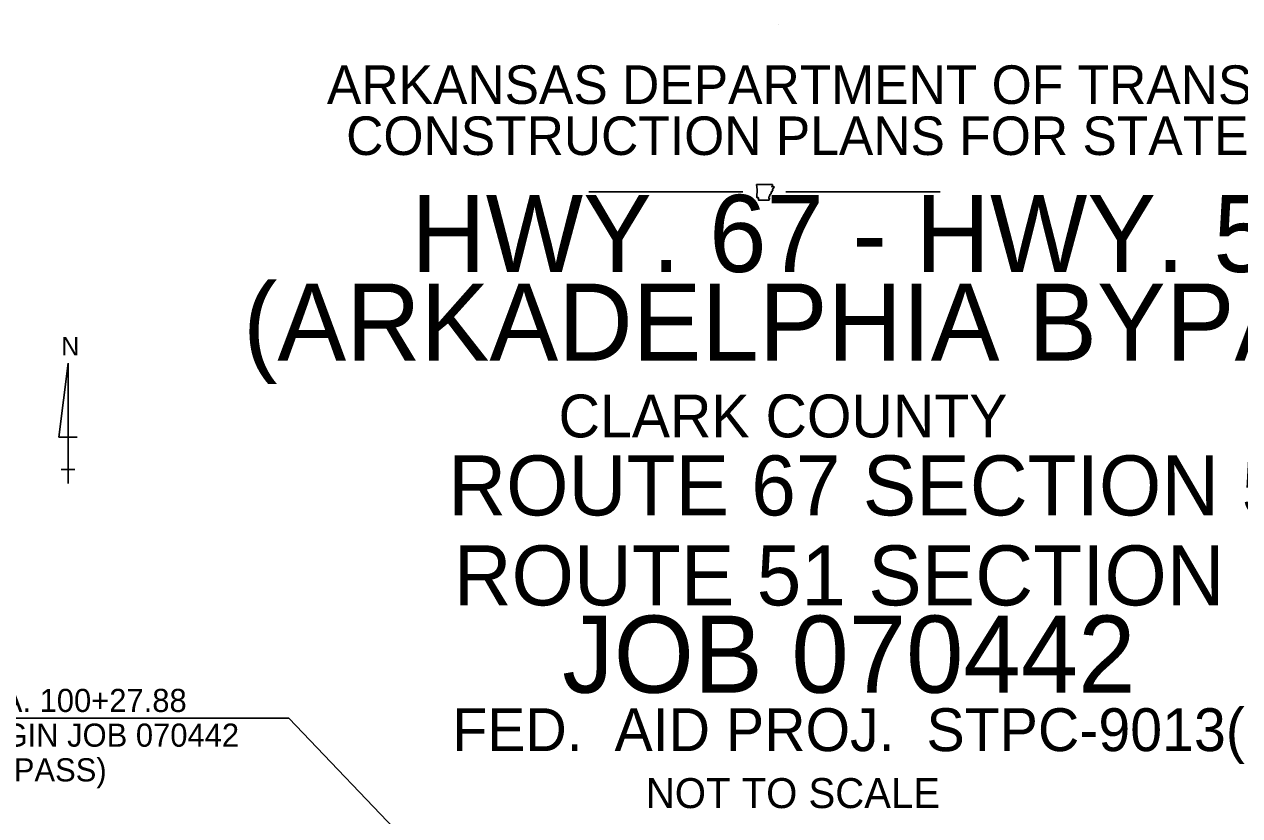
# Model space of a CAD drawing. Extents: x 813775 to 1157140, y 1757555 to 1979907.
# Drawn here: x 897210 to 1039048, y 1887546 to 1979907 of the extents above; entities that cross this region are included whole.
import ezdxf

# ---------------------------------------------------------------- set-up
doc = ezdxf.new("R2010")
doc.units = 0
doc.layers.add('1', color=7, linetype='Continuous')
doc.layers.add('R_Draft', color=7, linetype='Continuous')

msp = doc.modelspace()

# ---------------------------------------------------------------- linework, layer by layer
at = {"layer": '1'}
msp.add_line((985264.2783168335, 1979906.6062498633), (985264.2783168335, 1979906.6062498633), dxfattribs=at)
msp.add_line((985264.2783168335, 1979906.6062498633), (985264.2783168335, 1979906.6062498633), dxfattribs=at)
at = {"layer": 'R_Draft'}
for p, q in [((963082.4982804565, 1960363.5333469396), (981082.498282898, 1960363.5333469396)), ((986082.4982804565, 1960363.5333469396), (1004082.498282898, 1960363.5333469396)), ((902316.5839318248, 1940365.3942293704), (901236.5839318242, 1931725.394229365)), ((902316.5839318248, 1926325.3942296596), (902316.5839318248, 1940365.3942293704)), ((901236.5839318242, 1931725.394229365), (903396.5839318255, 1931725.394229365)), ((901501.5839318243, 1927965.3942296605), (903121.5839318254, 1927965.3942296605)), ((928075.3350066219, 1898928.1496111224), (888711.8381773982, 1898928.1496111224)), ((982982.4770436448, 1841464.5562002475), (928075.3350066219, 1898928.1496111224))]:
    msp.add_line(p, q, dxfattribs=at)
for points in [[(982650.88148172, 1961195.2289559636), (983196.6189818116, 1961194.8914559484), (983675.531481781, 1961195.9039559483), (984240.5064818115, 1961204.678955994), (984502.4064817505, 1961210.7539559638)], [(982690.3689817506, 1959718.6664559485), (982720.7439818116, 1960634.3039559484), (982650.88148172, 1961195.2289559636)], [(984421.406481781, 1960947.1664559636), (984677.5689818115, 1960960.3289559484)], [(984114.6189817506, 1959389.2664559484), (982877.6814817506, 1959391.2914559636), (982877.0064818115, 1959664.3289559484)]]:
    msp.add_lwpolyline(points, dxfattribs=at)
for points in [[(984398.7939818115, 1960300.8539559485), (984391.031481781, 1960291.0664559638), (984379.5564818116, 1960297.1414559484), (984379.5564818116, 1960305.2414559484), (984381.2439818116, 1960313.678955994), (984377.1939818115, 1960319.0789559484), (984370.1064818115, 1960316.7164559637), (984370.1064818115, 1960306.2539559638), (984369.4314818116, 1960296.1289559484), (984367.406481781, 1960281.6164559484), (984372.13148172, 1960277.2289559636), (984382.9314818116, 1960275.8789559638), (984390.69398172, 1960273.8539559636), (984395.4189818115, 1960266.0914559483), (984395.0814818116, 1960256.6414559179), (984391.3689818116, 1960247.5289559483), (984385.9689817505, 1960240.1039559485), (984377.531481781, 1960237.4039559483), (984370.781481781, 1960241.7914559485), (984368.08148172, 1960250.5664559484), (984365.0439818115, 1960258.3289559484), (984359.3064817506, 1960264.0664559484), (984353.2314818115, 1960257.6539559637), (984351.8814818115, 1960245.8414559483), (984352.2189817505, 1960235.7164559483), (984352.2189817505, 1960221.8789559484), (984360.9939817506, 1960212.7664559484), (984366.39398172, 1960202.3039559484), (984364.70648172, 1960192.8539559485), (984358.29398172, 1960181.7164559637), (984355.5939817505, 1960171.9289559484), (984352.8939818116, 1960158.7664559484), (984353.2314818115, 1960144.2539559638), (984350.8689817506, 1960130.0789559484), (984346.14398172, 1960120.6289559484), (984337.3689817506, 1960112.8664559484), (984331.63148172, 1960107.803955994), (984326.906481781, 1960102.7414559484), (984324.54398172, 1960092.616455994), (984322.85648172, 1960085.5289559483), (984316.4439818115, 1960077.0914559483), (984311.38148172, 1960076.4164559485), (984307.33148172, 1960079.7914559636), (984305.9814818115, 1960085.5289559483), (984305.9814818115, 1960091.2664559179), (984303.281481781, 1960097.0039559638), (984294.8439817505, 1960099.3664559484), (984288.0939817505, 1960099.0289559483), (984285.0564818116, 1960094.3039559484), (984289.4439818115, 1960081.1414559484), (984291.1314818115, 1960072.7039559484), (984288.76898172, 1960061.2289559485), (984290.1189817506, 1960059.8789559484), (984277.9689817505, 1960053.4664559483), (984268.1814818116, 1960052.4539559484), (984260.08148172, 1960050.0914559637), (984252.31898172, 1960045.0289559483), (984248.6064818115, 1960037.6039559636), (984243.20648172, 1960031.5289559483), (984238.48148172, 1960025.7914559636), (984232.0689818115, 1960023.0914559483), (984224.9814818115, 1960024.4414559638), (984215.531481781, 1960025.4539559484), (984210.13148172, 1960018.7039559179), (984211.81898172, 1960008.9164559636), (984218.2314818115, 1960003.178955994), (984227.6814818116, 1960000.4789559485), (984237.4689817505, 1960001.1539559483), (984246.9189818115, 1960002.1664559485), (984255.6939818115, 1959997.4414559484), (984254.00648172, 1959988.3289559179), (984245.5689818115, 1959983.9414559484), (984233.0814818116, 1959982.5914559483), (984222.9564818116, 1959983.6039559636), (984210.8064818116, 1959980.9039559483), (984204.73148172, 1959973.1414559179), (984208.10648172, 1959961.3289559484), (984221.2689818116, 1959956.6039559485), (984227.3439817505, 1959945.4664559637), (984227.6814818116, 1959935.0039559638), (984223.2939818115, 1959921.1664559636), (984217.2189817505, 1959914.7539559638), (984205.4064817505, 1959912.053955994), (984196.29398172, 1959910.3664559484), (984194.94398172, 1959894.8414559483), (984190.89398172, 1959887.0789559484), (984183.8064817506, 1959884.7164559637), (984173.6814817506, 1959889.7789559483), (984167.6064818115, 1959892.1414559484), (984160.1814817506, 1959895.5164559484), (984150.73148172, 1959901.2539559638), (984143.6439818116, 1959900.241455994), (984145.66898172, 1959885.3914559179), (984146.3439817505, 1959884.7164559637), (984154.44398172, 1959873.5789559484), (984162.5439818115, 1959864.8039559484), (984166.25648172, 1959854.3414559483)], [(984545.26898172, 1960635.3164559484), (984546.6189818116, 1960625.5289559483), (984540.8814818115, 1960615.0664559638), (984538.85648172, 1960604.6039559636), (984539.8689817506, 1960594.1414559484), (984529.0689818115, 1960588.4039559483), (984519.6189818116, 1960581.6539559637), (984525.01898172, 1960573.5539559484), (984535.1439818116, 1960566.1289559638), (984545.26898172, 1960560.3914559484), (984551.6814818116, 1960554.6539559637), (984553.3689818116, 1960540.8164559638), (984555.0564818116, 1960532.0414559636), (984558.4314818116, 1960519.8914559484), (984559.7814817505, 1960511.4539559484), (984553.70648172, 1960501.3289559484), (984546.6189818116, 1960499.3039559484), (984539.1939818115, 1960501.6664559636), (984530.4189818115, 1960502.3414559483), (984523.33148172, 1960495.5914559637), (984518.2689818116, 1960486.1414559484), (984513.2064818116, 1960476.6914559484), (984509.4939818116, 1960468.5914559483), (984505.781481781, 1960459.8164559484), (984498.35648172, 1960449.6914559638), (984489.2439818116, 1960448.0039559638), (984478.4439818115, 1960445.303955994), (984472.0314817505, 1960437.8789559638), (984473.0439818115, 1960425.3914559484), (984479.1189817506, 1960416.9539559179), (984483.843981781, 1960406.4914559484), (984487.218981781, 1960397.3789559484), (984485.531481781, 1960385.9039559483), (984480.8064817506, 1960377.4664559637), (984474.73148172, 1960372.4039559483), (984472.0314817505, 1960361.6039559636), (984467.64398172, 1960353.5039559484), (984463.5939817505, 1960350.8039559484), (984455.4939817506, 1960351.4789559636), (984446.718981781, 1960353.1664559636), (984439.29398172, 1960352.4914559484), (984432.20648172, 1960348.7789559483), (984425.1189817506, 1960351.1414559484), (984417.6939818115, 1960359.241455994), (984411.6189817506, 1960365.3164559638), (984404.8689818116, 1960367.6789559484), (984397.7814817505, 1960363.9664559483), (984396.4314817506, 1960352.8289559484), (984399.8064818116, 1960341.3539559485), (984402.8439817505, 1960325.8289559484), (984399.8064818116, 1960316.3789559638), (984398.7939818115, 1960300.8539559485)], [(984502.4064817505, 1961210.7539559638), (984504.0939817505, 1961195.9039559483), (984508.81898172, 1961188.1414559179), (984509.4939818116, 1961173.9664559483), (984515.2314818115, 1961167.8914559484), (984525.01898172, 1961161.8164559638), (984533.7939818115, 1961152.0289559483), (984535.8189818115, 1961140.5539559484), (984533.1189817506, 1961128.741455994), (984532.4439818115, 1961115.5789559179), (984531.0939817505, 1961104.1039559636), (984529.0689818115, 1961093.6414559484), (984520.9689817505, 1961085.2039559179), (984513.2064818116, 1961079.1289559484), (984506.1189818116, 1961072.0414559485), (984501.0564818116, 1961064.6164559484), (984492.281481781, 1961056.5164559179), (984483.5064818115, 1961048.0789559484), (984476.41898172, 1961040.6539559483), (984469.3314818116, 1961031.2039559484), (984465.95648172, 1961020.7414559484), (984458.19398172, 1961013.3164559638), (984452.1189817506, 1961006.5664559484), (984444.0189818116, 1960997.4539559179), (984439.9689817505, 1960988.3414559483), (984432.20648172, 1960977.8789559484), (984430.51898172, 1960967.7539559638), (984425.45648172, 1960959.6539559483), (984425.1189817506, 1960958.3039559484)], [(984673.85648172, 1960959.9914559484), (984677.5689818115, 1960960.3289559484), (984689.0439818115, 1960948.1789559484), (984694.1064818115, 1960938.053955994), (984701.5314817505, 1960932.3164559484), (984709.9689817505, 1960929.2789559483), (984716.3814818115, 1960921.5164559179), (984720.76898172, 1960913.0789559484), (984718.406481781, 1960905.6539559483), (984708.9564818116, 1960904.9789559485), (984698.4939818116, 1960903.2914559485), (984688.3689817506, 1960903.6289559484), (984680.2689818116, 1960896.8789559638), (984687.69398172, 1960887.7664559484), (984697.4814818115, 1960879.3289559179), (984700.1814818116, 1960870.2164559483), (984694.7814817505, 1960861.4414559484), (984683.98148172, 1960856.7164559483), (984673.51898172, 1960852.6664559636), (984664.0689818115, 1960844.5664559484), (984659.6814817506, 1960836.8039559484), (984649.2189817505, 1960833.428955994), (984638.4189818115, 1960830.3914559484), (984628.968981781, 1960829.3789559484), (984618.16898172, 1960827.3539559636), (984607.70648172, 1960822.2914559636), (984603.3189818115, 1960813.5164559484), (984604.6689818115, 1960801.0289559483), (984604.33148172, 1960787.866455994), (984615.468981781, 1960783.4789559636), (984625.25648172, 1960783.1414559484), (984634.7064818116, 1960778.0789559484), (984633.69398172, 1960770.6539559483), (984626.60648172, 1960761.2039559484), (984618.16898172, 1960753.7789559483), (984609.73148172, 1960750.0664559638), (984601.968981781, 1960742.9789559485), (984604.6689818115, 1960735.8914559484), (984611.7564818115, 1960731.1664559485), (984616.8189818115, 1960723.4039559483), (984616.14398172, 1960716.3164559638), (984608.04398172, 1960711.2539559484), (984599.26898172, 1960713.2789559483), (984592.8564818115, 1960721.7164559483), (984585.4314817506, 1960724.4164559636), (984579.0189818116, 1960727.4539559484), (984571.593981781, 1960723.0664559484), (984571.593981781, 1960713.2789559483), (984568.8939818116, 1960702.8164559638), (984571.25648172, 1960695.0539559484), (984574.2939818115, 1960684.2539559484), (984573.9564818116, 1960676.1539559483), (984571.25648172, 1960664.6789559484), (984565.5189818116, 1960652.866455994), (984558.7689818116, 1960649.1539559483), (984556.0689818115, 1960661.9789559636), (984554.718981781, 1960672.4414559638), (984550.66898172, 1960678.5164559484), (984545.26898172, 1960678.8539559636), (984538.1814817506, 1960673.7914559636), (984530.4189818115, 1960666.0289559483), (984520.63148172, 1960657.5914559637), (984514.8939818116, 1960649.1539559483), (984517.9314818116, 1960638.6914559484), (984525.3564818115, 1960635.9914559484), (984531.0939817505, 1960638.0164559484), (984534.1314818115, 1960644.7664559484), (984539.8689817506, 1960645.7789559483), (984545.26898172, 1960635.3164559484)], [(982877.0064818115, 1959664.3289559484), (982878.35648172, 1959663.6539559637), (982871.9439818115, 1959668.0414559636), (982863.1689818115, 1959672.4289559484), (982853.38148172, 1959673.1039559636), (982840.8939818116, 1959674.7914559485), (982830.4314818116, 1959675.803955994), (982819.6314818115, 1959682.8914559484), (982808.1564817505, 1959675.4664559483), (982795.3314818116, 1959670.0664559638), (982787.906481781, 1959676.1414559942), (982778.1189818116, 1959672.0914559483), (982771.3689818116, 1959674.116455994), (982759.5564817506, 1959666.0164559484), (982748.4189818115, 1959669.0539559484), (982740.31898172, 1959666.6914559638), (982730.19398172, 1959667.0289559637), (982728.16898172, 1959678.5039559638), (982718.3814818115, 1959680.1914559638), (982709.94398172, 1959684.9164559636), (982704.20648172, 1959696.7289559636), (982700.156481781, 1959705.8414559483), (982690.3689817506, 1959718.6664559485)], [(984166.25648172, 1959854.3414559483), (984162.88148172, 1959846.5789559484), (984159.1689818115, 1959833.0789559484), (984160.1814817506, 1959821.6039559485), (984165.2439818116, 1959811.8164559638), (984173.3439817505, 1959806.4164559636), (984182.1189817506, 1959798.6539559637), (984181.4439818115, 1959786.8414559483), (984176.3814818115, 1959782.4539559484), (984164.56898172, 1959785.4914559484), (984155.4564818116, 1959789.5414559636), (984147.69398172, 1959787.1789559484), (984137.23148172, 1959782.116455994), (984129.468981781, 1959781.1039559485), (984129.8064817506, 1959764.9039559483), (984140.26898172, 1959753.4289559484), (984149.38148172, 1959753.4289559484), (984159.8439817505, 1959752.0789559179), (984163.5564818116, 1959739.9289559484), (984157.4814818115, 1959729.8039559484), (984147.35648172, 1959724.7414559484), (984134.531481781, 1959730.8164559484), (984125.4189818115, 1959737.2289559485), (984116.3064817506, 1959743.3039559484), (984104.8314818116, 1959746.3414559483), (984098.4189818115, 1959744.9914559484), (984095.38148172, 1959730.8164559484), (984100.7814817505, 1959717.9914559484), (984109.5564818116, 1959709.2164559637), (984117.6564817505, 1959697.7414559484), (984116.3064817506, 1959689.303955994), (984110.2314818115, 1959686.9414559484), (984099.4314817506, 1959684.5789559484), (984093.0189818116, 1959681.2039559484), (984091.3314818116, 1959678.5039559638), (984094.7064818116, 1959667.0289559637), (984097.7439817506, 1959654.5414559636), (984097.7439817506, 1959645.0914559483), (984094.031481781, 1959636.3164559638), (984088.29398172, 1959622.8164559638), (984088.9689817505, 1959614.0414559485), (984093.0189818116, 1959609.9914559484), (984098.0814818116, 1959611.3414559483), (984104.8314818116, 1959616.0664559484), (984109.2189817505, 1959621.4664559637), (984112.9314817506, 1959628.2164559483), (984120.0189818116, 1959633.9539559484), (984128.7939818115, 1959628.8914559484), (984130.8189818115, 1959618.428955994), (984125.7564818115, 1959609.3164559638), (984118.6689818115, 1959605.2664559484), (984109.89398172, 1959601.8914559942), (984103.4814818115, 1959594.4664559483), (984105.1689818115, 1959585.6914559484), (984110.2314818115, 1959580.9664559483), (984122.718981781, 1959583.3289559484), (984131.156481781, 1959587.0414559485), (984135.88148172, 1959591.7664559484), (984141.6189818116, 1959597.5039559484), (984144.6564817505, 1959603.241455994), (984149.04398172, 1959609.3164559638), (984156.8064817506, 1959611.0039559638), (984160.5189818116, 1959605.9414559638), (984159.1689818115, 1959594.4664559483), (984154.44398172, 1959583.6664559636), (984148.0314817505, 1959574.553955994), (984140.9439818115, 1959568.1414559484), (984132.1689818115, 1959554.3039559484), (984133.8564818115, 1959541.4789559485), (984137.23148172, 1959531.0164559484), (984141.95648172, 1959522.9164559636), (984150.0564818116, 1959524.6039559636), (984159.1689818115, 1959525.616455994), (984164.56898172, 1959521.2289559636), (984163.8939818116, 1959511.7789559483), (984157.1439818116, 1959502.6664559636), (984150.73148172, 1959493.8914559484), (984147.35648172, 1959481.741455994), (984148.7064818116, 1959473.3039559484), (984148.7064818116, 1959465.5414559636), (984146.00648172, 1959457.1039559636), (984141.281481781, 1959452.3789559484), (984128.7939818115, 1959452.7164559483), (984115.6314818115, 1959454.0664559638), (984108.5439818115, 1959450.0164559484), (984109.89398172, 1959438.5414559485), (984117.6564817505, 1959430.1039559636), (984123.0564817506, 1959425.7164559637), (984130.8189818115, 1959416.2664559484), (984134.19398172, 1959408.5039559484), (984133.1814818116, 1959401.7539559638), (984128.45648172, 1959396.0164559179), (984114.6189817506, 1959389.2664559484)]]:
    msp.add_spline(points, degree=3, dxfattribs=at)

# ---------------------------------------------------------------- texts
for s, height, p in [('ARKANSAS DEPARTMENT OF TRANSPORTATION ', 4499.999999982, (932527.1185389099, 1970613.5333457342)), ('CONSTRUCTION PLANS FOR STATE HIGHWAY', 4499.999999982, (934769.7366491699, 1964653.5333457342)), ('HWY. 67 - HWY. 51 ', 9000, (942368.6758379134, 1950998.6423942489)), ('(ARKADELPHIA BYPASS) (S)', 9000, (922738.754578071, 1940652.1857013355)), ('N', 2159.999999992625, (901536.5839306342, 1941265.3942293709)), ('CLARK COUNTY', 5000, (959560.178030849, 1931695.740552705)), ('ROUTE 67 SECTION 5', 6999.999999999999, (946682.7024131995, 1922590.7523285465)), ('ROUTE 51 SECTION 1 ', 6999.999999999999, (947316.560680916, 1912090.7523285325)), ('JOB 070442', 9000, (959980.6509356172, 1901897.6960523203)), ('STA. 100+27.88', 2699.9999999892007, (889966.1515797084, 1899647.384107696)), ('FED.  AID PROJ.  STPC-9013(10)', 5000, (947143.6037294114, 1895083.1708500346)), ('BEGIN JOB 070442', 2699.9999999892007, (889966.1515797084, 1895597.3841077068)), ('(BYPASS)', 2699.9999999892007, (889966.1515797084, 1891547.3841077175)), ('NOT TO SCALE', 3499.9999999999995, (969747.0988538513, 1888432.625934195))]:
    msp.add_text(s, height=height, dxfattribs=at).set_placement(p)

doc.saveas('drawing.dxf')
